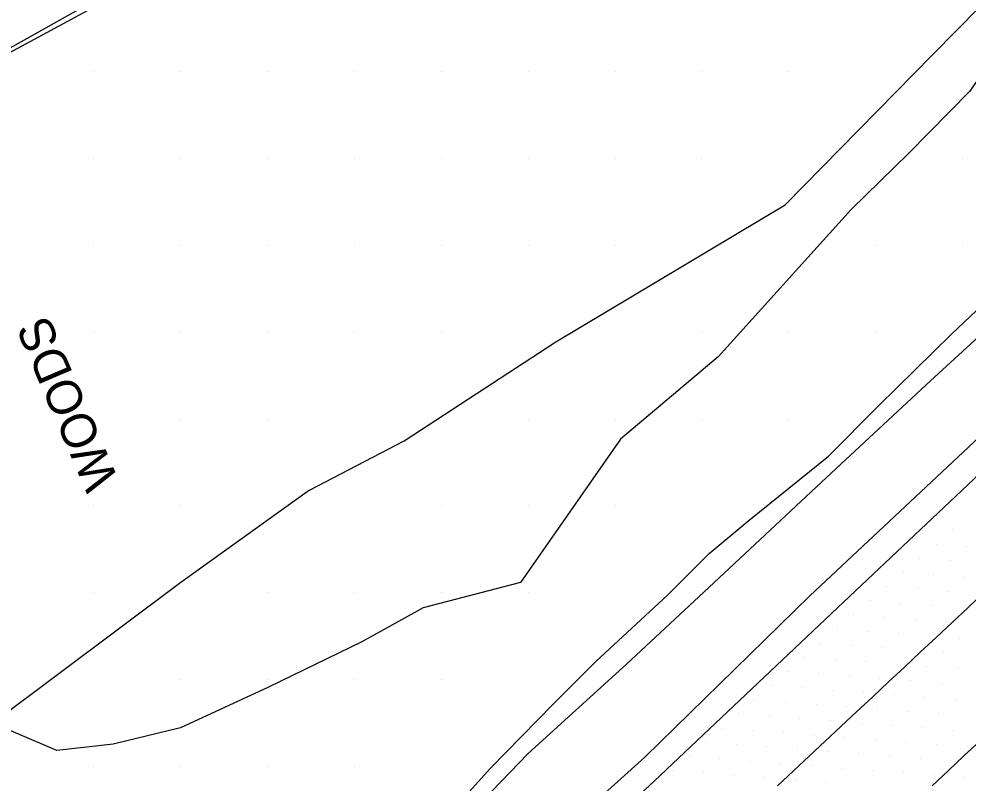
# Model space of a CAD drawing. Extents: x 1548934 to 1561348, y 809680 to 824075.
# Drawn here: x 1551931.4 to 1552040.6, y 810978.1 to 811066.1 of the extents above; entities that cross this region are included whole.
import ezdxf

# ---------------------------------------------------------------- set-up
doc = ezdxf.new("R2010")
doc.units = 0
for name, color, linetype in [('E_NCDOT_Vertical_Profile_Ground_Line', 7, 'Continuous'), ('Exist DTM QL2 LIDAR Elevation Point', 7, 'Continuous'), ('Exist DTM Scan Elevation Point', 7, 'Continuous'), ('Exist Vegetation Woods Line', 7, 'Continuous'), ('Exist Vegetation Woods Line Text', 7, 'Continuous'), ('P_RDY_Dimension_Text', 7, 'Continuous'), ('P_RDY_Terminator_Cell', 7, 'Continuous'), ('PH Exist DTM Breakline', 7, 'Continuous')]:
    doc.layers.add(name, color=color, linetype=linetype)

msp = doc.modelspace()

# ---------------------------------------------------------------- linework, layer by layer
at = {"layer": 'E_NCDOT_Vertical_Profile_Ground_Line'}
msp.add_lwpolyline([(1551916.37, 810897.06), (1551938.53, 810917.27), (1551960.65, 810937.52), (1551982.56, 810958.01), (1552004.5, 810978.34), (1552026.32, 810998.92), (1552048.09, 811019.51), (1552069.81, 811040.13), (1552091.66, 811060.69), (1552113.49, 811081.33), (1552135.26, 811101.95), (1552157.03, 811122.67), (1552170.31, 811135.33)], dxfattribs=at)
at = {"layer": 'Exist DTM QL2 LIDAR Elevation Point'}
for p, q in [((1551940.01, 811060.02), (1551940.01, 811060.02)), ((1551950.01, 811060.02), (1551950.01, 811060.02)), ((1551960.02, 811060.02), (1551960.02, 811060.02)), ((1551970.02, 811060.02), (1551970.02, 811060.02)), ((1551980.02, 811060.02), (1551980.02, 811060.02)), ((1551990.02, 811060.02), (1551990.02, 811060.02)), ((1552000.02, 811060.02), (1552000.02, 811060.02)), ((1552010.02, 811060.02), (1552010.02, 811060.02)), ((1552020.02, 811060.02), (1552020.02, 811060.02)), ((1551940.01, 811050.01), (1551940.01, 811050.01)), ((1551950.01, 811050.01), (1551950.01, 811050.01)), ((1551960.02, 811050.01), (1551960.02, 811050.01)), ((1551970.02, 811050.01), (1551970.02, 811050.01)), ((1551980.02, 811050.01), (1551980.02, 811050.01)), ((1551990.02, 811050.01), (1551990.02, 811050.01)), ((1552000.02, 811050.01), (1552000.02, 811050.01)), ((1552010.02, 811050.01), (1552010.02, 811050.01)), ((1552040.02, 811050.01), (1552040.02, 811050.01)), ((1551940.01, 811040.01), (1551940.01, 811040.01)), ((1551950.01, 811040.01), (1551950.01, 811040.01)), ((1551960.02, 811040.01), (1551960.02, 811040.01)), ((1551970.02, 811040.01), (1551970.02, 811040.01)), ((1551980.02, 811040.01), (1551980.02, 811040.01)), ((1551990.02, 811040.01), (1551990.02, 811040.01)), ((1552000.02, 811040.01), (1552000.02, 811040.01)), ((1552030.02, 811040.01), (1552030.02, 811040.01)), ((1552040.02, 811040.01), (1552040.02, 811040.01)), ((1551940.01, 811030.01), (1551940.01, 811030.01)), ((1551950.01, 811030.01), (1551950.01, 811030.01)), ((1551960.02, 811030.01), (1551960.02, 811030.01)), ((1551970.02, 811030.01), (1551970.02, 811030.01)), ((1551980.02, 811030.01), (1551980.02, 811030.01)), ((1552010.02, 811030.01), (1552010.02, 811030.01)), ((1552020.02, 811030.01), (1552020.02, 811030.01)), ((1552030.02, 811030.01), (1552030.02, 811030.01)), ((1551940.01, 811020.01), (1551940.01, 811020.01)), ((1551950.01, 811020.01), (1551950.01, 811020.01)), ((1551960.02, 811020.01), (1551960.02, 811020.01)), ((1551990.02, 811020.01), (1551990.02, 811020.01)), ((1552000.02, 811020.01), (1552000.02, 811020.01)), ((1552010.02, 811020.01), (1552010.02, 811020.01)), ((1552020.02, 811020.01), (1552020.02, 811020.01)), ((1551940.01, 811010.01), (1551940.01, 811010.01)), ((1551950.01, 811010.01), (1551950.01, 811010.01)), ((1551980.02, 811010.01), (1551980.02, 811010.01)), ((1551990.02, 811010.01), (1551990.02, 811010.01)), ((1552000.02, 811010.01), (1552000.02, 811010.01)), ((1551940.01, 811000.01), (1551940.01, 811000.01)), ((1551960.02, 811000.01), (1551960.02, 811000.01)), ((1551970.02, 811000.01), (1551970.02, 811000.01)), ((1551980.02, 811000.01), (1551980.02, 811000.01)), ((1551990.02, 811000.01), (1551990.02, 811000.01)), ((1551950.01, 810990.01), (1551950.01, 810990.01)), ((1551960.02, 810990.01), (1551960.02, 810990.01)), ((1551970.02, 810990.01), (1551970.02, 810990.01)), ((1551980.02, 810990.01), (1551980.02, 810990.01)), ((1551940.01, 810980.01), (1551940.01, 810980.01)), ((1551950.01, 810980.01), (1551950.01, 810980.01)), ((1551960.02, 810980.01), (1551960.02, 810980.01)), ((1551970.02, 810980.01), (1551970.02, 810980.01))]:
    msp.add_line(p, q, dxfattribs=at)
at = {"layer": 'Exist DTM Scan Elevation Point'}
for p, q in [((1552038.88, 811007.26), (1552038.88, 811007.26)), ((1552036.98, 811005.63), (1552036.98, 811005.63)), ((1552040.51, 811005.36), (1552040.51, 811005.36)), ((1552035.09, 811004), (1552035.09, 811004)), ((1552038.61, 811003.73), (1552038.61, 811003.73)), ((1552033.19, 811002.37), (1552033.19, 811002.37)), ((1552036.71, 811002.1), (1552036.71, 811002.1)), ((1552040.24, 811001.83), (1552040.24, 811001.83)), ((1552031.29, 811000.74), (1552031.29, 811000.74)), ((1552034.82, 811000.47), (1552034.82, 811000.47)), ((1552038.34, 811000.2), (1552038.34, 811000.2)), ((1552029.4, 810999.11), (1552029.4, 810999.11)), ((1552032.92, 810998.84), (1552032.92, 810998.84)), ((1552036.45, 810998.58), (1552036.45, 810998.58)), ((1552039.97, 810998.31), (1552039.97, 810998.31)), ((1552027.5, 810997.48), (1552027.5, 810997.48)), ((1552031.03, 810997.22), (1552031.03, 810997.22)), ((1552034.55, 810996.95), (1552034.55, 810996.95)), ((1552038.08, 810996.68), (1552038.08, 810996.68)), ((1552025.6, 810995.85), (1552025.6, 810995.85)), ((1552029.13, 810995.59), (1552029.13, 810995.59)), ((1552032.65, 810995.32), (1552032.65, 810995.32)), ((1552036.18, 810995.05), (1552036.18, 810995.05)), ((1552039.7, 810994.78), (1552039.7, 810994.78)), ((1552023.71, 810994.23), (1552023.71, 810994.23)), ((1552027.23, 810993.96), (1552027.23, 810993.96)), ((1552030.76, 810993.69), (1552030.76, 810993.69)), ((1552034.28, 810993.42), (1552034.28, 810993.42)), ((1552021.81, 810992.6), (1552021.81, 810992.6)), ((1552025.34, 810992.33), (1552025.34, 810992.33)), ((1552037.81, 810993.15), (1552037.81, 810993.15)), ((1552028.86, 810992.06), (1552028.86, 810992.06)), ((1552032.39, 810991.79), (1552032.39, 810991.79)), ((1552035.91, 810991.52), (1552035.91, 810991.52)), ((1552039.44, 810991.26), (1552039.44, 810991.26)), ((1552019.92, 810990.97), (1552019.92, 810990.97)), ((1552023.44, 810990.7), (1552023.44, 810990.7)), ((1552026.97, 810990.43), (1552026.97, 810990.43)), ((1552030.49, 810990.16), (1552030.49, 810990.16)), ((1552018.02, 810989.34), (1552018.02, 810989.34)), ((1552021.54, 810989.07), (1552021.54, 810989.07)), ((1552034.02, 810989.9), (1552034.02, 810989.9)), ((1552037.54, 810989.63), (1552037.54, 810989.63)), ((1552025.07, 810988.8), (1552025.07, 810988.8)), ((1552028.59, 810988.53), (1552028.59, 810988.53)), ((1552032.12, 810988.27), (1552032.12, 810988.27)), ((1552035.64, 810988), (1552035.64, 810988)), ((1552016.12, 810987.71), (1552016.12, 810987.71)), ((1552019.65, 810987.44), (1552019.65, 810987.44)), ((1552023.17, 810987.17), (1552023.17, 810987.17)), ((1552026.7, 810986.91), (1552026.7, 810986.91)), ((1552039.17, 810987.73), (1552039.17, 810987.73)), ((1552014.23, 810986.08), (1552014.23, 810986.08)), ((1552017.75, 810985.81), (1552017.75, 810985.81)), ((1552030.22, 810986.64), (1552030.22, 810986.64)), ((1552033.75, 810986.37), (1552033.75, 810986.37)), ((1552037.27, 810986.1), (1552037.27, 810986.1)), ((1552021.28, 810985.54), (1552021.28, 810985.54)), ((1552024.8, 810985.28), (1552024.8, 810985.28)), ((1552028.33, 810985.01), (1552028.33, 810985.01)), ((1552031.85, 810984.74), (1552031.85, 810984.74)), ((1552012.33, 810984.45), (1552012.33, 810984.45)), ((1552015.86, 810984.18), (1552015.86, 810984.18)), ((1552019.38, 810983.92), (1552019.38, 810983.92)), ((1552022.9, 810983.65), (1552022.9, 810983.65)), ((1552035.38, 810984.47), (1552035.38, 810984.47)), ((1552038.9, 810984.21), (1552038.9, 810984.21)), ((1552010.43, 810982.82), (1552010.43, 810982.82)), ((1552013.96, 810982.55), (1552013.96, 810982.55)), ((1552026.43, 810983.38), (1552026.43, 810983.38)), ((1552029.95, 810983.11), (1552029.95, 810983.11)), ((1552033.48, 810982.84), (1552033.48, 810982.84)), ((1552037.01, 810982.58), (1552037.01, 810982.58)), ((1552040.53, 810982.31), (1552040.53, 810982.31)), ((1552017.48, 810982.29), (1552017.48, 810982.29)), ((1552021.01, 810982.02), (1552021.01, 810982.02)), ((1552024.53, 810981.75), (1552024.53, 810981.75)), ((1552028.06, 810981.48), (1552028.06, 810981.48)), ((1552008.54, 810981.19), (1552008.54, 810981.19)), ((1552012.06, 810980.93), (1552012.06, 810980.93)), ((1552015.59, 810980.66), (1552015.59, 810980.66)), ((1552019.11, 810980.39), (1552019.11, 810980.39)), ((1552031.58, 810981.22), (1552031.58, 810981.22)), ((1552035.11, 810980.95), (1552035.11, 810980.95)), ((1552038.63, 810980.68), (1552038.63, 810980.68)), ((1552006.64, 810979.56), (1552006.64, 810979.56)), ((1552010.17, 810979.3), (1552010.17, 810979.3)), ((1552022.64, 810980.12), (1552022.64, 810980.12)), ((1552026.16, 810979.85), (1552026.16, 810979.85)), ((1552029.69, 810979.59), (1552029.69, 810979.59)), ((1552033.21, 810979.32), (1552033.21, 810979.32)), ((1552036.74, 810979.05), (1552036.74, 810979.05)), ((1552013.69, 810979.03), (1552013.69, 810979.03)), ((1552017.22, 810978.76), (1552017.22, 810978.76)), ((1552020.74, 810978.49), (1552020.74, 810978.49)), ((1552024.27, 810978.23), (1552024.27, 810978.23)), ((1552040.26, 810978.78), (1552040.26, 810978.78))]:
    msp.add_line(p, q, dxfattribs=at)
at = {"layer": 'Exist Vegetation Woods Line'}
for points in [[(1551977.93, 810998.3), (1551970.88, 810994.36), (1551960.15, 810989.16), (1551950.01, 810984.47), (1551942.26, 810982.58), (1551935.79, 810981.88), (1551927.04, 810985.6), (1551917.17, 810997.94), (1551912.39, 811001.64), (1551905.64, 811006.2), (1551898.94, 811010.16), (1551894.03, 811013.82), (1551889.51, 811019.9), (1551884.86, 811024.1), (1551880.67, 811028.77), (1551884.61, 811037.75), (1551893.7, 811042.39), (1551949.83, 811072.75)], [(1552046.76, 811066.19), (1552040.8, 811057.7), (1552033.83, 811050.61), (1552027.2, 811044.14), (1552011.87, 811027.19), (1552000.65, 811017.69), (1551989.12, 811001.2), (1551977.93, 810998.3)]]:
    msp.add_lwpolyline(points, dxfattribs=at)
at = {"layer": 'P_RDY_Dimension_Text'}
msp.add_lwpolyline([(1551792.63, 810879.89), (1551798.87, 810886.61), (1551791.81, 810954.68), (1551790.16, 810983.57), (1551796.35, 810987.52), (1551966.16, 811082.82)], dxfattribs=at)
at = {"layer": 'P_RDY_Terminator_Cell'}
for points in [[(1552018.71, 810977.8), (1552020.54, 810979.51), (1552022.36, 810981.22), (1552024.19, 810982.93), (1552026.01, 810984.63), (1552027.84, 810986.34), (1552029.67, 810988.05), (1552031.49, 810989.76), (1552033.32, 810991.46), (1552035.14, 810993.17), (1552036.97, 810994.88), (1552038.8, 810996.59), (1552040.61, 810998.3), (1552042.43, 811000.02)], [(1552041.98, 810982.96), (1552040.16, 810981.24), (1552038.35, 810979.52), (1552036.52, 810977.81)]]:
    msp.add_lwpolyline(points, dxfattribs=at)
at = {"layer": 'PH Exist DTM Breakline'}
for points in [[(1551964.87, 811011.81), (1551975.75, 811017.5), (1551993.21, 811028.9), (1552019.58, 811044.66), (1552036.56, 811061.92), (1552052.87, 811078.54), (1552058.72, 811085.17), (1552064.45, 811100.69), (1552073.41, 811111.32), (1552085.56, 811125.66), (1552095.43, 811130.85), (1552112.53, 811138.38), (1552127.13, 811144.62), (1552136.95, 811150.64)], [(1551976.06, 810969.12), (1551985.65, 810979.8), (1551992.95, 810987.24), (1551997.82, 810992.11), (1552006.04, 810999.75), (1552010.84, 811004.55), (1552015.46, 811008.38), (1552024.58, 811015.75), (1552030.32, 811021.53), (1552038.79, 811029.81), (1552047.22, 811037.78), (1552058.63, 811048.94), (1552067.82, 811057.98), (1552078.4, 811068.68), (1552086.91, 811077.17), (1552097.9, 811087.2), (1552108.72, 811097.64), (1552127.22, 811115.39), (1552138.18, 811125.76), (1552150.17, 811138.94)], [(1551976.37, 810967.37), (1551990.02, 810981.53), (1552001.33, 810991.79), (1552010.23, 811000.09), (1552024.35, 811013.28), (1552036.33, 811024.4), (1552051.57, 811038.4), (1552060.65, 811048.24), (1552069.18, 811056.77), (1552080.24, 811066.77), (1552090.88, 811077.64), (1552102.68, 811090.03), (1552112.72, 811099.39), (1552122.5, 811106.78), (1552140.47, 811123.19), (1552153.6, 811136.59)], [(1552161.51, 811130.57), (1552144.97, 811115.31), (1552129.09, 811100.89), (1552111.27, 811084.33), (1552094.29, 811067.65), (1552076.64, 811051.15), (1552059.63, 811035.39), (1552041.29, 811017.37), (1552022.43, 810999.68), (1552003.45, 810981.1), (1551990.64, 810969.55), (1551980.75, 810963.34)], [(1551964.87, 811011.81), (1551950.05, 811001.19), (1551928.64, 810985.19), (1551911.37, 810973.98), (1551899.79, 810966.08), (1551880.25, 810951.2), (1551869.51, 810942.95), (1551844.01, 810925.31), (1551827.48, 810911.47), (1551810.29, 810896.27), (1551800.43, 810887.11), (1551798.7, 810886.52), (1551796.47, 810886.72), (1551794.87, 810885.71)]]:
    msp.add_lwpolyline(points, dxfattribs=at)

# ---------------------------------------------------------------- texts
at = {"layer": 'Exist Vegetation Woods Line Text'}
msp.add_text('WOODS', height=4.02, rotation=113.1736, dxfattribs=at).set_placement((1551942.96, 811012.89))

doc.saveas('drawing.dxf')
